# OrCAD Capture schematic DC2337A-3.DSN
size Custom; title: OFF-LINE NO-OPTO; rev: 3; note: DEMO CIRCUIT 2337A
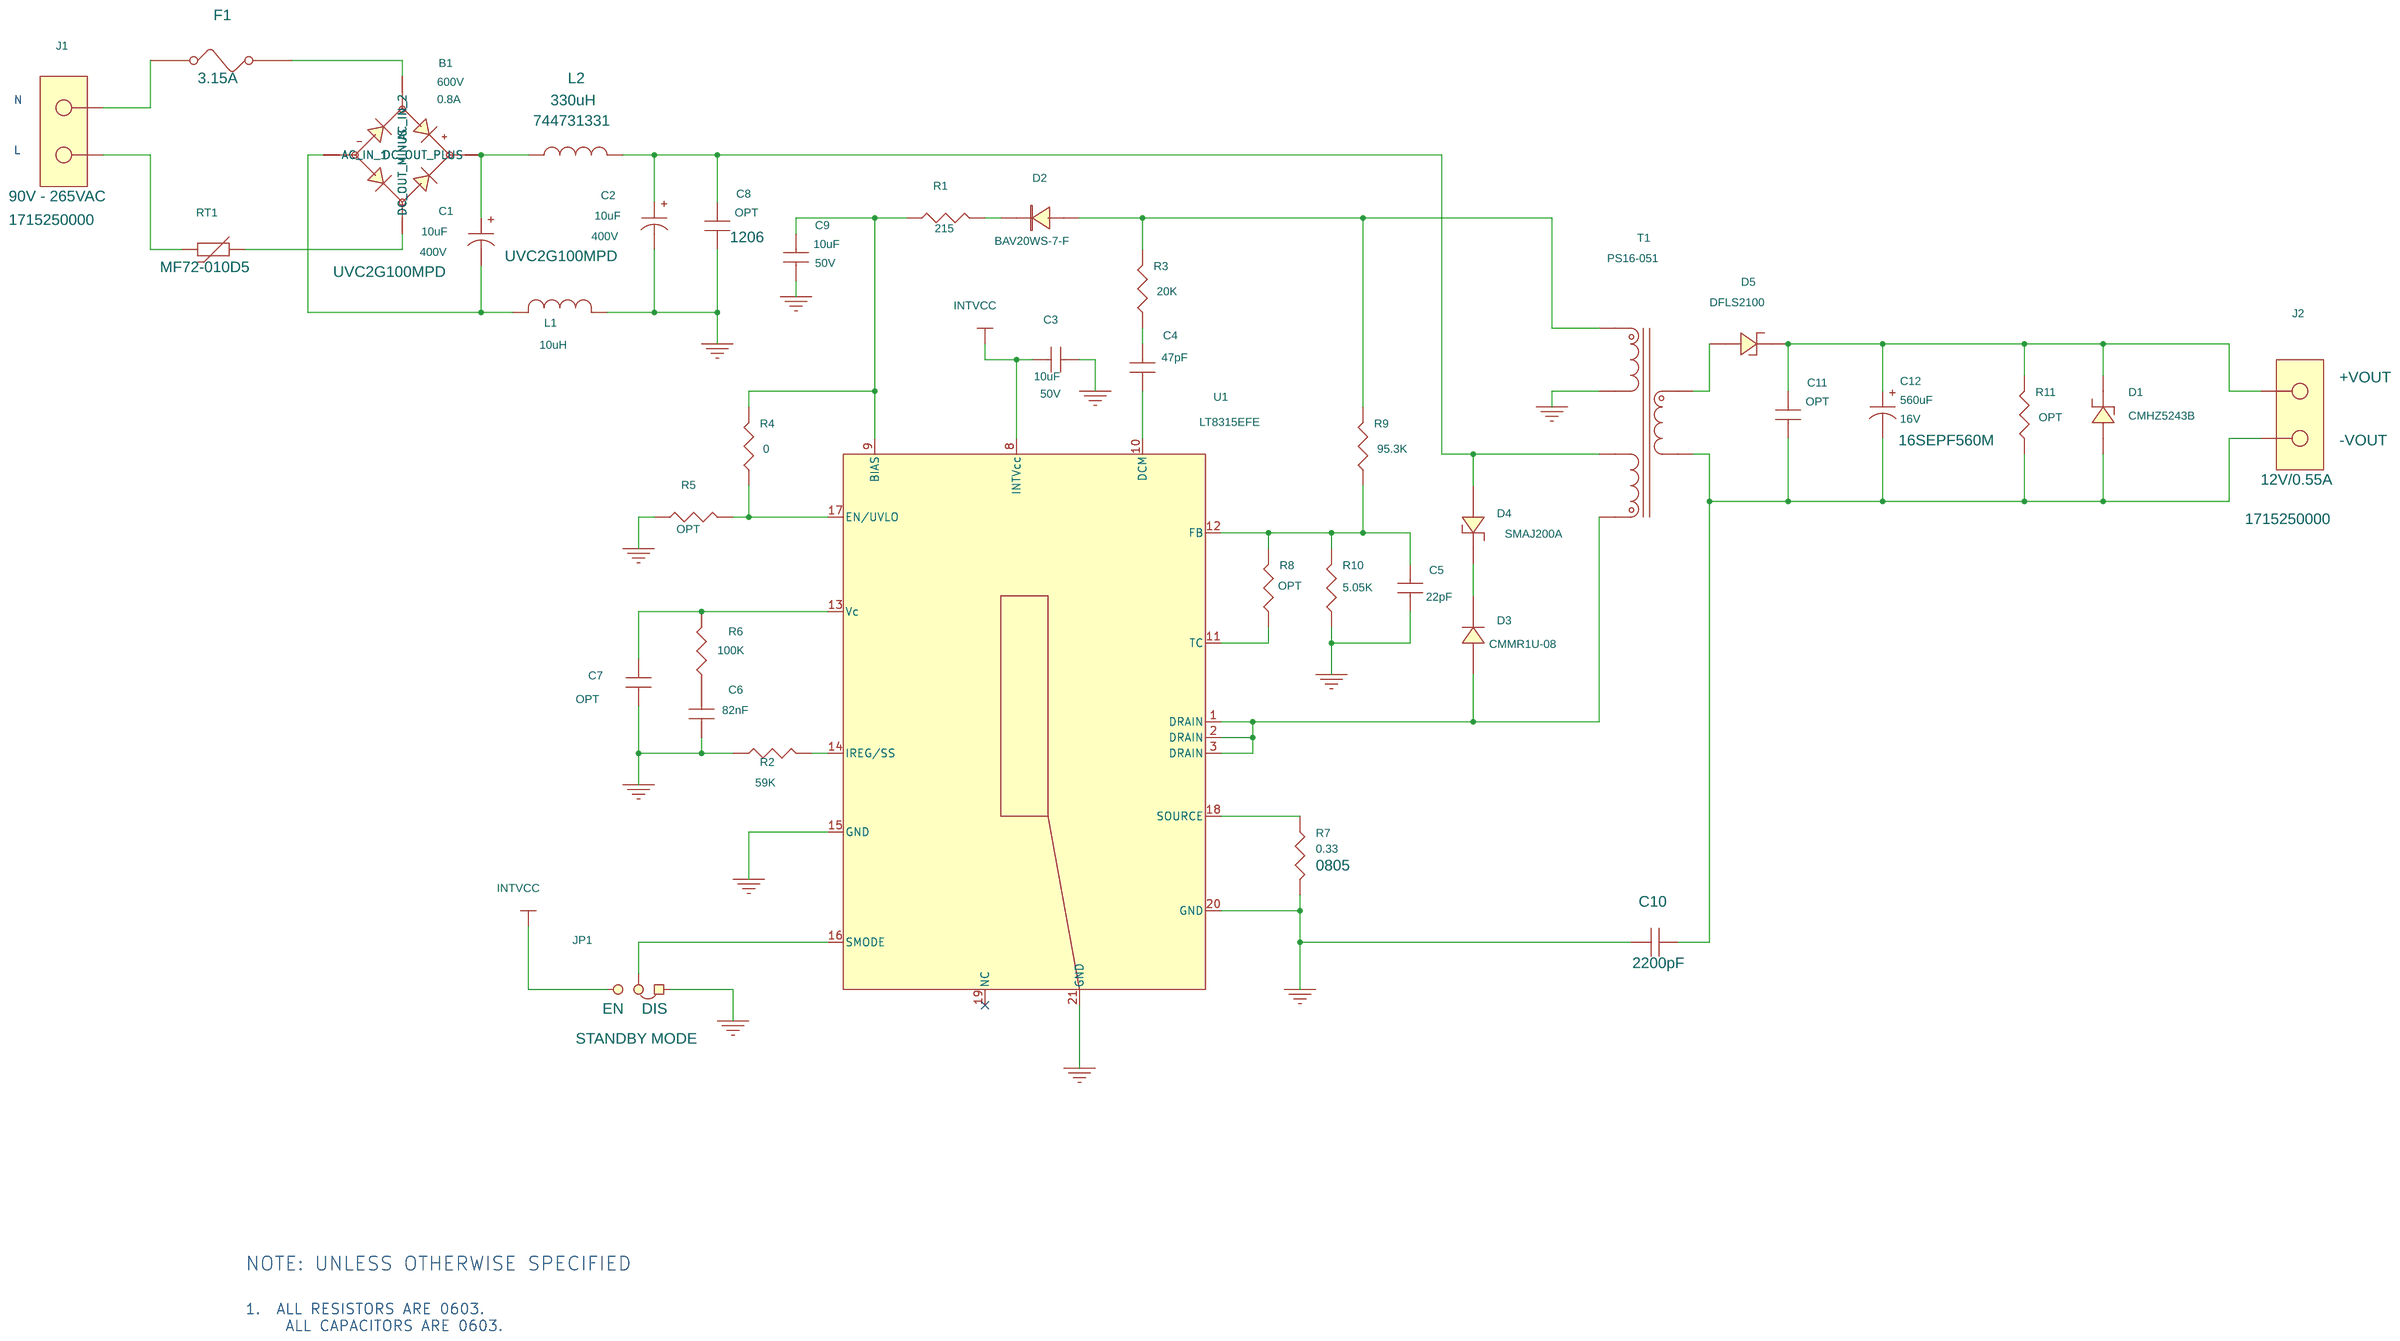
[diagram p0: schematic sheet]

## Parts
B1  0.8A  [BRDG_DDS-INC_HD01-6]
C1  10uF  [CAP-TH-10X12.5]
C2  10uF  [CAP-TH-10X12.5]
C3  10uF  [1210]
C4  47pF  [0603]
C5  22pF  [0603]
C6  82nF  [0603]
C7  OPT  [0603]
C8  OPT  [1206]
C9  10uF  [1210]
C10  2200pF  [CAP\VISHAY\440L]
C11  OPT  [1210]
C12  560uF  [CAP-OS-CON-E12]
D1  CMHZ5243B  [SOD-123]
D2  400mA/150V  [SOD-323]
D3  CMMR1U-08  [SOD-123F]
D4  SMAJ200A  [SMA]
D5  DFLS2100  [POWER-DI-123]
F1  3.15A  [COOPER-FUSE-SS-5H-1A]
J1  CON-2PIN  [CONN\WDMLLR\1715250000]
J2  CON-2PIN  [CONN\WDMLLR\1715250000]
JP1  JP3X1/079\NO\12  [JP3X1/079]
L1  10uH  [1008]
L2  330uH  [IND-744731331]
R1  215  [0603]
R2  59K  [0603]
R3  20K  [0603]
R4  0  [0603]
R5  OPT  [0603]
R6  100K  [0603]
R7  0.33  [0805]
R8  OPT  [0603]
R9  95.3K  [0603]
R10  5.05K  [0603]
R11  OPT  [0603]
RT1  MF72-010D5  [CANTHERM-MF72-D5]
T1  PS16-051  [TRAN-SUMIDA-RM6-PS16-051]
U1  LT8315EFE  [TSSOP20FE(16)]

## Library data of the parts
B1 = BR805D_0: 1st Part Field: 600V; 4th Part Field: DIODES INC.; 5th Part Field: HD06-T; 7th Part Field: RECTIFIER,   BRIDGE; Package Type: Mini Dip; Part Number: DIODES INC. HD06-T
C1 C2 = CAP+: 1ST PART FIELD: 400V; 4TH PART FIELD: Nichicon; 5TH PART FIELD: UVC2G100MPD
C3 C8 C9 = CAP1210: 1ST PART FIELD: 50V
C4-C7 = CAP0805
C10 = CAP_NP: 1st Part Field: 400VAC; 2nd Part Field: 20%; 3rd Part Field: Y5U; 4th Part Field: VISHAY; 5th Part Field: 440LD22-R; 7th Part Field: Cap.,; Field1: Y; Part Number: VISHAY 440LD22-R
C11 = CAP1210
C12 = CAP+: 1ST PART FIELD: 16V; 2ND PART FIELD: 20%; 3RD PART FIELD: ALUM.,; 5TH PART FIELD: 16SEPF560M
D1 D4 D5 = CMDSH-3
D2 = BAV20W_0: 5th Part Field: BAV20WS-7-F
D3 = CMMR1U-02
F1 = FUSE: FUSE, 3.15A; 4th Part Field: COOPER BUSSMANN; 5th Part Field: SS-5H-3.15A; 7th Part Field: Fuse,
J1 = CON-2PIN: 1st Part Field: 1715250000; 2nd Part Field: 90V - 265VAC
J2 = CON-2PIN: 1st Part Field: 1715250000; 2nd Part Field: 90V - 265VAC; 3rd Part Field: +VOUT; 4th Part Field: -VOUT; 5th Part Field: 12V/0.55A
JP1 = JP3X1_079_NO_12: 1st Part Field: DIS; 2nd Part Field: EN; 3rd Part Field: STANDBY MODE
L1 = IND-TOKO-DB320C: 4TH PART FIELD: TDK; 5TH PART FIELD: MLP2520S100S
L2 = INDUCTOR: 4th Part Field: WURTH ELECTRONIK; 5th Part Field: 744731331; 7th Part Field: IND.,
R1 R7 = AAC-1206
R2-R6 R8-R11 = AAC-0805
RT1 = VARISTOR: 4th Part Field: CANTHERM; 7th Part Field: ICL; Package Type: 13.5MM Radial
T1 = TRANS-P0926_3: 4TH PART FIELD: SUMIDA; 7TH PART FIELD: TRANS.,
U1 = LT8315FEF_8

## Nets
GND: C2.2 C3.2 C5.1 C6.1 C7.1 C8.2 C9.2 C10.2 JP1.1 L1.2 R2.1 R5.1 R7.2 R10.1 T1.6 U1.15(GND) U1.20(GND) U1.21(GND)
INTVCC: C3.1 JP1.3 U1.8(INTVcc)
N16958387: B1.3(AC_IN_2) F1.2
N16958443: B1.4(DC_OUT_MINUS) RT1.1
N16958750: B1.2(AC_IN_1) C1.2 L1.1
N16958975: C2.1 C8.1 D4.2(ANODE) L2.2 T1.1
N16958976: B1.1(DC_OUT_PLUS) C1.1 L2.1
N16960406: D2.2(a) R3.2 R9.2 T1.4
N16960446: D2.1(K) R1.2
N16960523: C9.1 R1.1 R4.2 U1.9(BIAS)
N16961884: R4.1 R5.2 U1.17(EN/UVLO)
N16962525: C7.2 R6.2 U1.13(Vc)
N16962993: R2.2 U1.14(IREG/SS)
N16972546: C5.2 R8.2 R9.1 R10.2 U1.12(FB)
N16972643: R8.1 U1.11(TC)
N16976418: D3.2(ANODE) T1.3 U1.1(DRAIN) U1.2(DRAIN) U1.3(DRAIN)
N16978946: D3.1(CATHODE) D4.1(CATHODE)
N16979240: R7.1 U1.18(SOURCE)
N16981256: C10.1 C11.2 C12.2 D1.2(ANODE) J2.2 R11.1 T1.10
N16983314: D5.2(ANODE) T1.12
N16984160: C11.1 C12.1 D1.1(CATHODE) D5.1(CATHODE) J2.1 R11.2
N17000777: JP1.2 U1.16(SMODE)
N17031076: C4.1 U1.10(DCM)
N17031690: C4.2 R3.1
N17041763: F1.1 J1.1
N17044269: J1.2 RT1.2
N17057255: C6.2 R6.1

Not connected (* = marked no-connect by the designer): U1 19(NC)*

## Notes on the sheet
- N
- L
- NOTE: UNLESS OTHERWISE SPECIFIED
- 1.  ALL RESISTORS ARE 0603.
       ALL CAPACITORS ARE 0603.
